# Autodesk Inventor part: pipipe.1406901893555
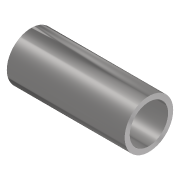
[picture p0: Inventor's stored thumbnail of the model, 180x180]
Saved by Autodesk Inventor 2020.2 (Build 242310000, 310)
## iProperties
Manager: www.cadconsulting.pl
Company: Fabian Stasiak CAD Consulting
IsCustomPart: 1
NAME: PIPING: JIS G 3458 Pipe
DATA: <meta><inlinegroups number="1" deflen="10"></inlinegroups><connections number="2"></connections><angles><a>3.14159265358979</a></angles></meta>
Created: 2014-08
Material: Stal, stopowa
Description: Rura
Document SubType Name: Modeling
Standard: JIS G 3458
Designer: F.Stasiak
Standards Organization: JIS
Language: pl-PL
Size Designation: 40 A x Sch 80 - 100
Categories: <MemberInstance><Categories><Category DisplayName="Rury cienko- i grubościenne" InternalName="4347fa0f-2144-441d-94cd-e3e15c92b736" Mnemonic="TUBEANDPIPE"><Cate
Stock Number: JIS G 3458 Rura 40 A x Sch 80
Density: 7.73 g/cm^3
Appearance: Częściowo polerowana
Catalog Web Link: www.expertbooks.pl
L: 118,000 mm
PL: 118,000 mm
Author: F.Stasiak
Subject: Zbiór ćwiczeń. Autodesk Inventor 2020. Kurs Professional
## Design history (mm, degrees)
sketch "Sketch1"
  geometry: C1 r 24.3 at (0, 0); C2 r 19.2 at (0, 0); 1 further point
  constraints: 2 centre point, 2 coincident, 1 concentric
  dimensions: "d0" = 48.6 diameter of C1 (= OD); "d1" = 38.4 diameter of C2 (= OD - 2 x t)
extrude "Extrusion1" new body sketch "Sketch1" distance "d2" = 118 (= L); taper "d3" = 0 deg
workaxis "Work Axis1"
workpoint "Work Point1"
workaxis "Work Axis2"
workpoint "Work Point2"
body "Solid1"
other parameters: "OD" = 48.6 [user parameter; used in 2 equation terms], "t" = 5.1 [user parameter; used in 1 equation term], "L" = 118 (= PL) [user parameter; used in 1 equation term], "ID" = 38.4 [user parameter], "PL" = 118 [user parameter; used in 1 equation term], "Size_Designation" = 12.345 [user parameter]
